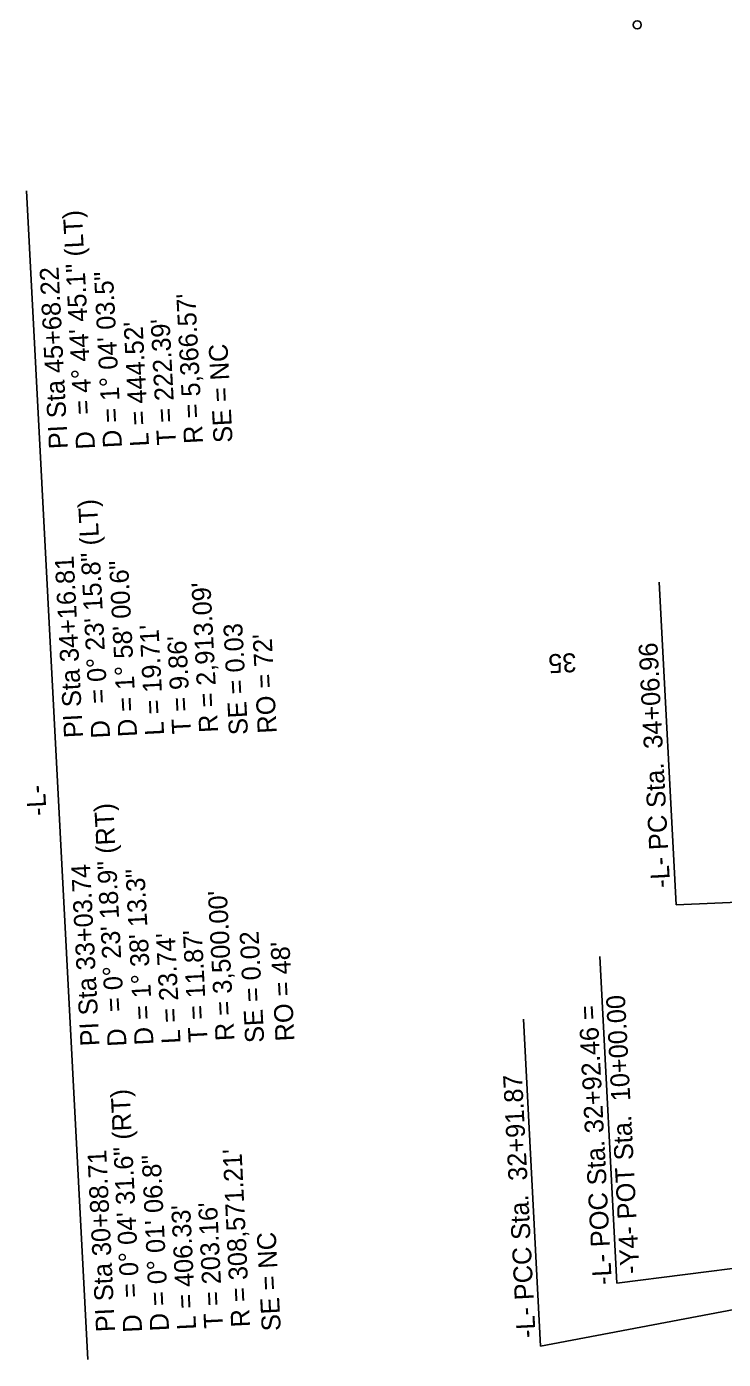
# Model space of a CAD drawing. Extents: x 2367848 to 2369479, y 800728 to 808616.
# Drawn here: x 2368339.2 to 2368596.9, y 803556.1 to 804048.8 of the extents above; entities that cross this region are included whole.
import ezdxf

# ---------------------------------------------------------------- set-up
doc = ezdxf.new("R2010")
doc.units = 0
for name, color, linetype in [('Prop Horizontal Alignment Curve and Spiral Data', 7, 'Continuous'), ('Prop Horizontal Alignment Station Label', 7, 'Continuous'), ('Prop Horizontal Alignment Tick Label', 7, 'Continuous')]:
    doc.layers.add(name, color=color, linetype=linetype)

msp = doc.modelspace()

# ---------------------------------------------------------------- linework, layer by layer
at = {"layer": 'Prop Horizontal Alignment Station Label'}
for p, q in [((2368361.84, 803556.08), (2368339.22, 803988.02)), ((2368579.43, 803724.11), (2368573.19, 803843.34)), ((2368837.43, 803734.96), (2368579.43, 803724.11)), ((2368557.52, 803584.23), (2368551.19, 803705.04)), ((2368529.29, 803560.99), (2368522.96, 803681.8)), ((2368842.34, 803620.05), (2368529.29, 803560.99)), ((2368843.81, 803620.63), (2368557.52, 803584.23))]:
    msp.add_line(p, q, dxfattribs=at)
msp.add_circle((2368565.04, 804049.45), 1.5, dxfattribs=at)

# ---------------------------------------------------------------- texts
at = {"layer": 'Prop Horizontal Alignment Curve and Spiral Data'}
for s, rotation, p in [('= 4%%d 44\' 45.1" (LT)', 92.9979, (2368363.54, 803905.47)), ('PI Sta 45+68.22', 92.9979, (2368354.49, 803892.8)), ('D = 1%%d 04\' 03.5"', 92.9979, (2368374.49, 803893.18)), ("R = 5,366.57'", 92.9979, (2368404.45, 803894.75)), ("L = 444.52'", 92.9979, (2368384.48, 803893.7)), ("T = 222.39'", 92.9979, (2368394.47, 803894.22)), ('SE = NC', 92.9979, (2368415.4, 803895.07)), ('D', 92.9979, (2368364.51, 803892.65)), ('= 0%%d 23\' 15.8" (LT)', 92.9979, (2368369.14, 803798.65)), ('PI Sta 34+16.81', 92.9979, (2368360.08, 803785.98)), ('D = 1%%d 58\' 00.6"', 92.9979, (2368380.09, 803786.35)), ("R = 2,913.09'", 92.9979, (2368410.05, 803787.92)), ("L = 19.71'", 92.9979, (2368390.08, 803786.88)), ('SE = 0.03', 92.9979, (2368421.1, 803787.07)), ("RO = 72'", 92.9979, (2368431.71, 803787.63)), ("T = 9.86'", 92.9979, (2368400.06, 803787.4)), ('D', 92.9979, (2368370.1, 803785.83)), ('-L-', 92.9979, (2368346.58, 803757.14)), ('= 0%%d 23\' 18.9" (RT)', 92.9979, (2368375.21, 803684.69)), ('PI Sta 33+03.74', 92.9979, (2368366.16, 803672.03)), ('D = 1%%d 38\' 13.3"', 92.9979, (2368386.16, 803672.4)), ("R = 3,500.00'", 92.9979, (2368416.12, 803673.97)), ("L = 23.74'", 92.9979, (2368396.15, 803672.92)), ("T = 11.87'", 92.9979, (2368406.14, 803673.45)), ('SE = 0.02', 92.9979, (2368427.1, 803673.24)), ("RO = 48'", 92.9979, (2368438.3, 803673.83)), ('D', 92.9979, (2368376.18, 803671.88)), ('= 0%%d 04\' 31.6" (RT)', 92.7929, (2368381.01, 803578.97)), ('PI Sta 30+88.71', 92.7929, (2368371.91, 803566.34)), ('D = 0%%d 01\' 06.8"', 92.7929, (2368391.92, 803566.64)), ("R = 308,571.21'", 92.7929, (2368421.89, 803568.1)), ("L = 406.33'", 92.7929, (2368401.91, 803567.13)), ("T = 203.16'", 92.7929, (2368411.9, 803567.61)), ('SE = NC', 92.9979, (2368433.22, 803566.7)), ('D', 92.7929, (2368381.94, 803566.15))]:
    msp.add_text(s, height=7, rotation=rotation, dxfattribs=at).set_placement(p)
at = {"layer": 'Prop Horizontal Alignment Station Label'}
for s, p in [('-L- PC Sta.  34+06.96', (2368577.21, 803730.55)), ('-Y4- POT Sta.  10+00.00', (2368565.86, 803587.8)), ('-L- POC Sta. 32+92.46 =', (2368555.66, 803583.75)), ('-L- PCC Sta.  32+91.87', (2368527.49, 803564.12))]:
    msp.add_text(s, height=7, rotation=92.9979, dxfattribs=at).set_placement(p)
at = {"layer": 'Prop Horizontal Alignment Tick Label'}
msp.add_text('35', height=7, rotation=182.7965, dxfattribs=at).set_placement((2368542.39, 803817.2))

doc.saveas('drawing.dxf')
